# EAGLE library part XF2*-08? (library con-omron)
OMRON FPC Connector Source : http://www.omron.com/ecb/products/pdf/fpc.pdf
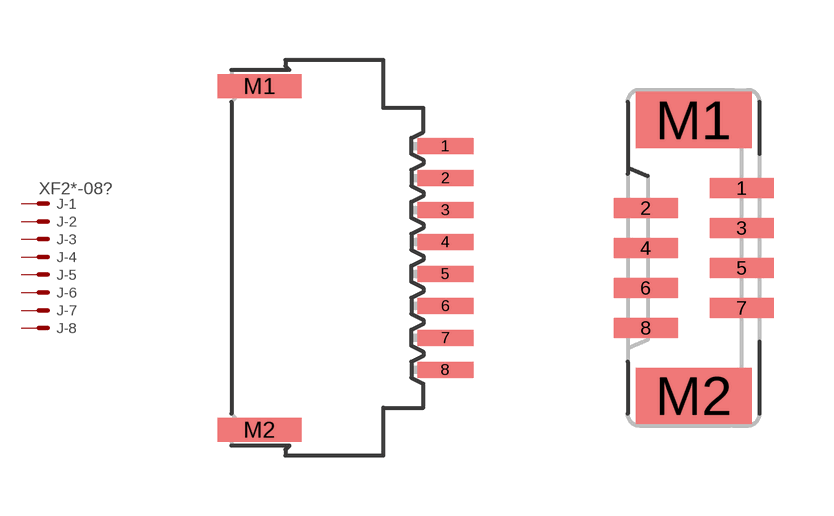
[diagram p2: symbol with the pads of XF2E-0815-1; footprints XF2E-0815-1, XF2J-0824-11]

Designator prefix J; gates -1=PV -2=P -3=P -4=P -5=P -6=P -7=P -8=P

## XF2E-0815-1 (MPN: XF2E-0815-1; OC_FARNELL: unknown; OC_NEWARK: 37M9451)  [XF2E-0815-1]
1  -1:MSV  pas
2  -2:MS  pas
3  -3:MS  pas
4  -4:MS  pas
5  -5:MS  pas
6  -6:MS  pas
7  -7:MS  pas
8  -8:MS  pas

## XF2J-0824-11 (MPN: XF2J-0824-11; OC_FARNELL: unknown; OC_NEWARK: 37M0811)  [XF2J-0824-11]
Pads as for XF2E-0815-1

## XF2J-0824-12 (OC_FARNELL: unknown; OC_NEWARK: unknown)  [XF2J-0824-12]
Pads as for XF2E-0815-1

## XF2L-0825-1 (MPN: XF2L-0825-1; OC_FARNELL: unknown; OC_NEWARK: 37M0872)  [XF2L-0825-1]
Pads as for XF2E-0815-1

## XF2L-0835-1 (MPN: XF2L-0835-1; OC_FARNELL: unknown; OC_NEWARK: 37M0874)  [XF2L-0835-1]
Pads as for XF2E-0815-1

## Footprint XF2E-0815-1 (pad centres in mm)
Non-ZIF Type (0.8 mm-pitch) Source : http://www.omron.com/ecb/products/pdf/fpc.pdf
smd 1.4 x 0.4: 1 2.54,2.8; 2 2.54,2; 3 2.54,1.2; 4 2.54,0.4; 5 2.54,-0.4; 6 2.54,-1.2; 7 2.54,-2; 8 2.54,-2.8
smd 2.1 x 0.6: M1 -2.11,4.3; M2 -2.11,-4.3

## Footprint XF2J-0824-11 (pad centres in mm)
ZIF Slide-locking Type (0.5 mm-pitch) Standard Source : http://www.omron.com/ecb/products/pdf/fpc.pdf
smd 1.6 x 0.5: 1 1.2,1.75; 2 -1.2,1.25; 3 1.2,0.75; 4 -1.2,0.25; 5 1.2,-0.25; 6 -1.2,-0.75; 7 1.2,-1.25; 8 -1.2,-1.75
smd 2.9 x 1.4: M1 0,3.45; M2 0,-3.45

## Footprint XF2J-0824-12 (pad centres in mm)
ZIF Slide-locking Type (0.5 mm-pitch) Reverse Source : http://www.omron.com/ecb/products/pdf/fpc.pdf
smd 1.6 x 0.5: 1 -1.2,1.75; 2 1.2,1.25; 3 -1.2,0.75; 4 1.2,0.25; 5 -1.2,-0.25; 6 1.2,-0.75; 7 -1.2,-1.25; 8 1.2,-1.75
smd 2.9 x 1.4: M1 0,3.45; M2 0,-3.45

## Footprint XF2L-0825-1 (pad centres in mm)
ZIF Slide-locking Type (0.5 mm-pitch) Upper-contact Type Source : http://www.omron.com/ecb/products/pdf/fpc.pdf
smd 1 x 0.25: 1 1.905,1.75; 2 1.905,1.25; 3 1.905,0.75; 4 1.905,0.25; 5 1.905,-0.25; 6 1.905,-0.75; 7 1.905,-1.25; 8 1.905,-1.75
smd 1.34 x 1: M1 0.18,4.138; M2 0.18,-4.138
